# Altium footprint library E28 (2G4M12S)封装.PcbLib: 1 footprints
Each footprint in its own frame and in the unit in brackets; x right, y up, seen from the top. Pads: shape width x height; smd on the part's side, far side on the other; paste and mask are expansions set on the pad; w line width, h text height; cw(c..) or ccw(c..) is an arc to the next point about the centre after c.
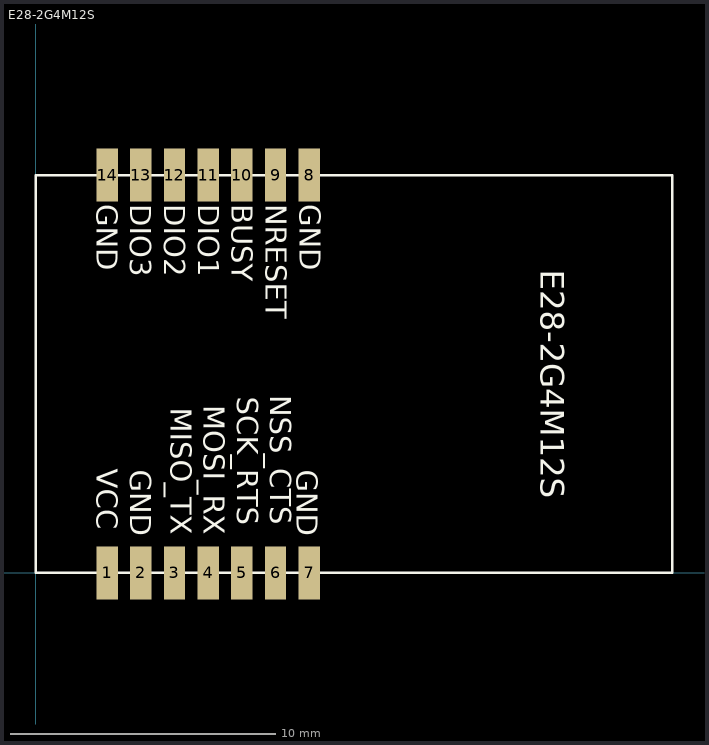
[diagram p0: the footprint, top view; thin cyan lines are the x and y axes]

## E28-2G4M12S [mm]
pads (14):
  rect 0.8x2 smd: 1(2.69,0) 2(3.96,0) 3(5.23,0) 4(6.5,0) 5(7.77,0) 6(9.04,0) 7(10.31,0) 8(10.31,15) 9(9.04,15) 10(7.77,15) 11(6.5,15) 12(5.23,15) 13(3.96,15) 14(2.69,15)
Top Overlay:
  lines w0.1: 0,0 0,15 24,15 24,0 0,0
  text "E28-2G4M12S" at 19.05,11.43 h0.9
  text "GND" at 2.29,13.9 h0.8
  text "DIO3" at 3.567,13.9 h0.8
  text "DIO2" at 4.843,13.9 h0.8
  text "DIO1" at 6.12,13.9 h0.8
  text "BUSY" at 7.397,13.9 h0.8
  text "NRESET" at 8.673,13.9 h0.8
  text "GND" at 9.95,13.9 h0.8
  text "GND" at 9.84,3.883 h0.8
  text "NSS_CTS" at 8.85,6.69 h0.8
  text "SCK_RTS" at 7.593,6.648 h0.8
  text "MOSI_RX" at 6.337,6.313 h0.8
  text "MISO_TX" at 5.08,6.229 h0.8
  text "GND" at 3.557,3.883 h0.8
  text "VCC" at 2.3,3.921 h0.8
